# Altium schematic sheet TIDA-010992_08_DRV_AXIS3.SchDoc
size 431 x 279 mm; Date: Not shown in title block; ApprovedBy: Not shown in title block; CheckedBy: Not shown in title block; Author: Not shown in title block; CompanyName: Not shown in title block; Engineer: Not shown in title block; Organization: Not shown in title block; Address1: Not shown in title block; Address2: Not shown in title block; Address3: Not shown in title block; Address4: Not shown in title block; DocumentNumber: 8; Revision: Use project parameter SCH_Rev; SheetNumber: 8; SheetTotal: 13; PageSetup: Record=PageOptions¦CenterHorizontal=True¦CenterVertical=True¦PrintScale=1.00¦XCorrection=1.00¦YCorrection=1.00¦PrintKind=0¦BorderSize=5000000¦LeftOffset=0¦BottomOffset=0¦Orientation=2¦PaperLength=1000¦PaperWidth=1000¦Scale=100¦PaperSource=15¦PrintQuality=600¦MediaType=1¦DitherType=10¦PaperKind=Letter¦PrintScaleMode=1
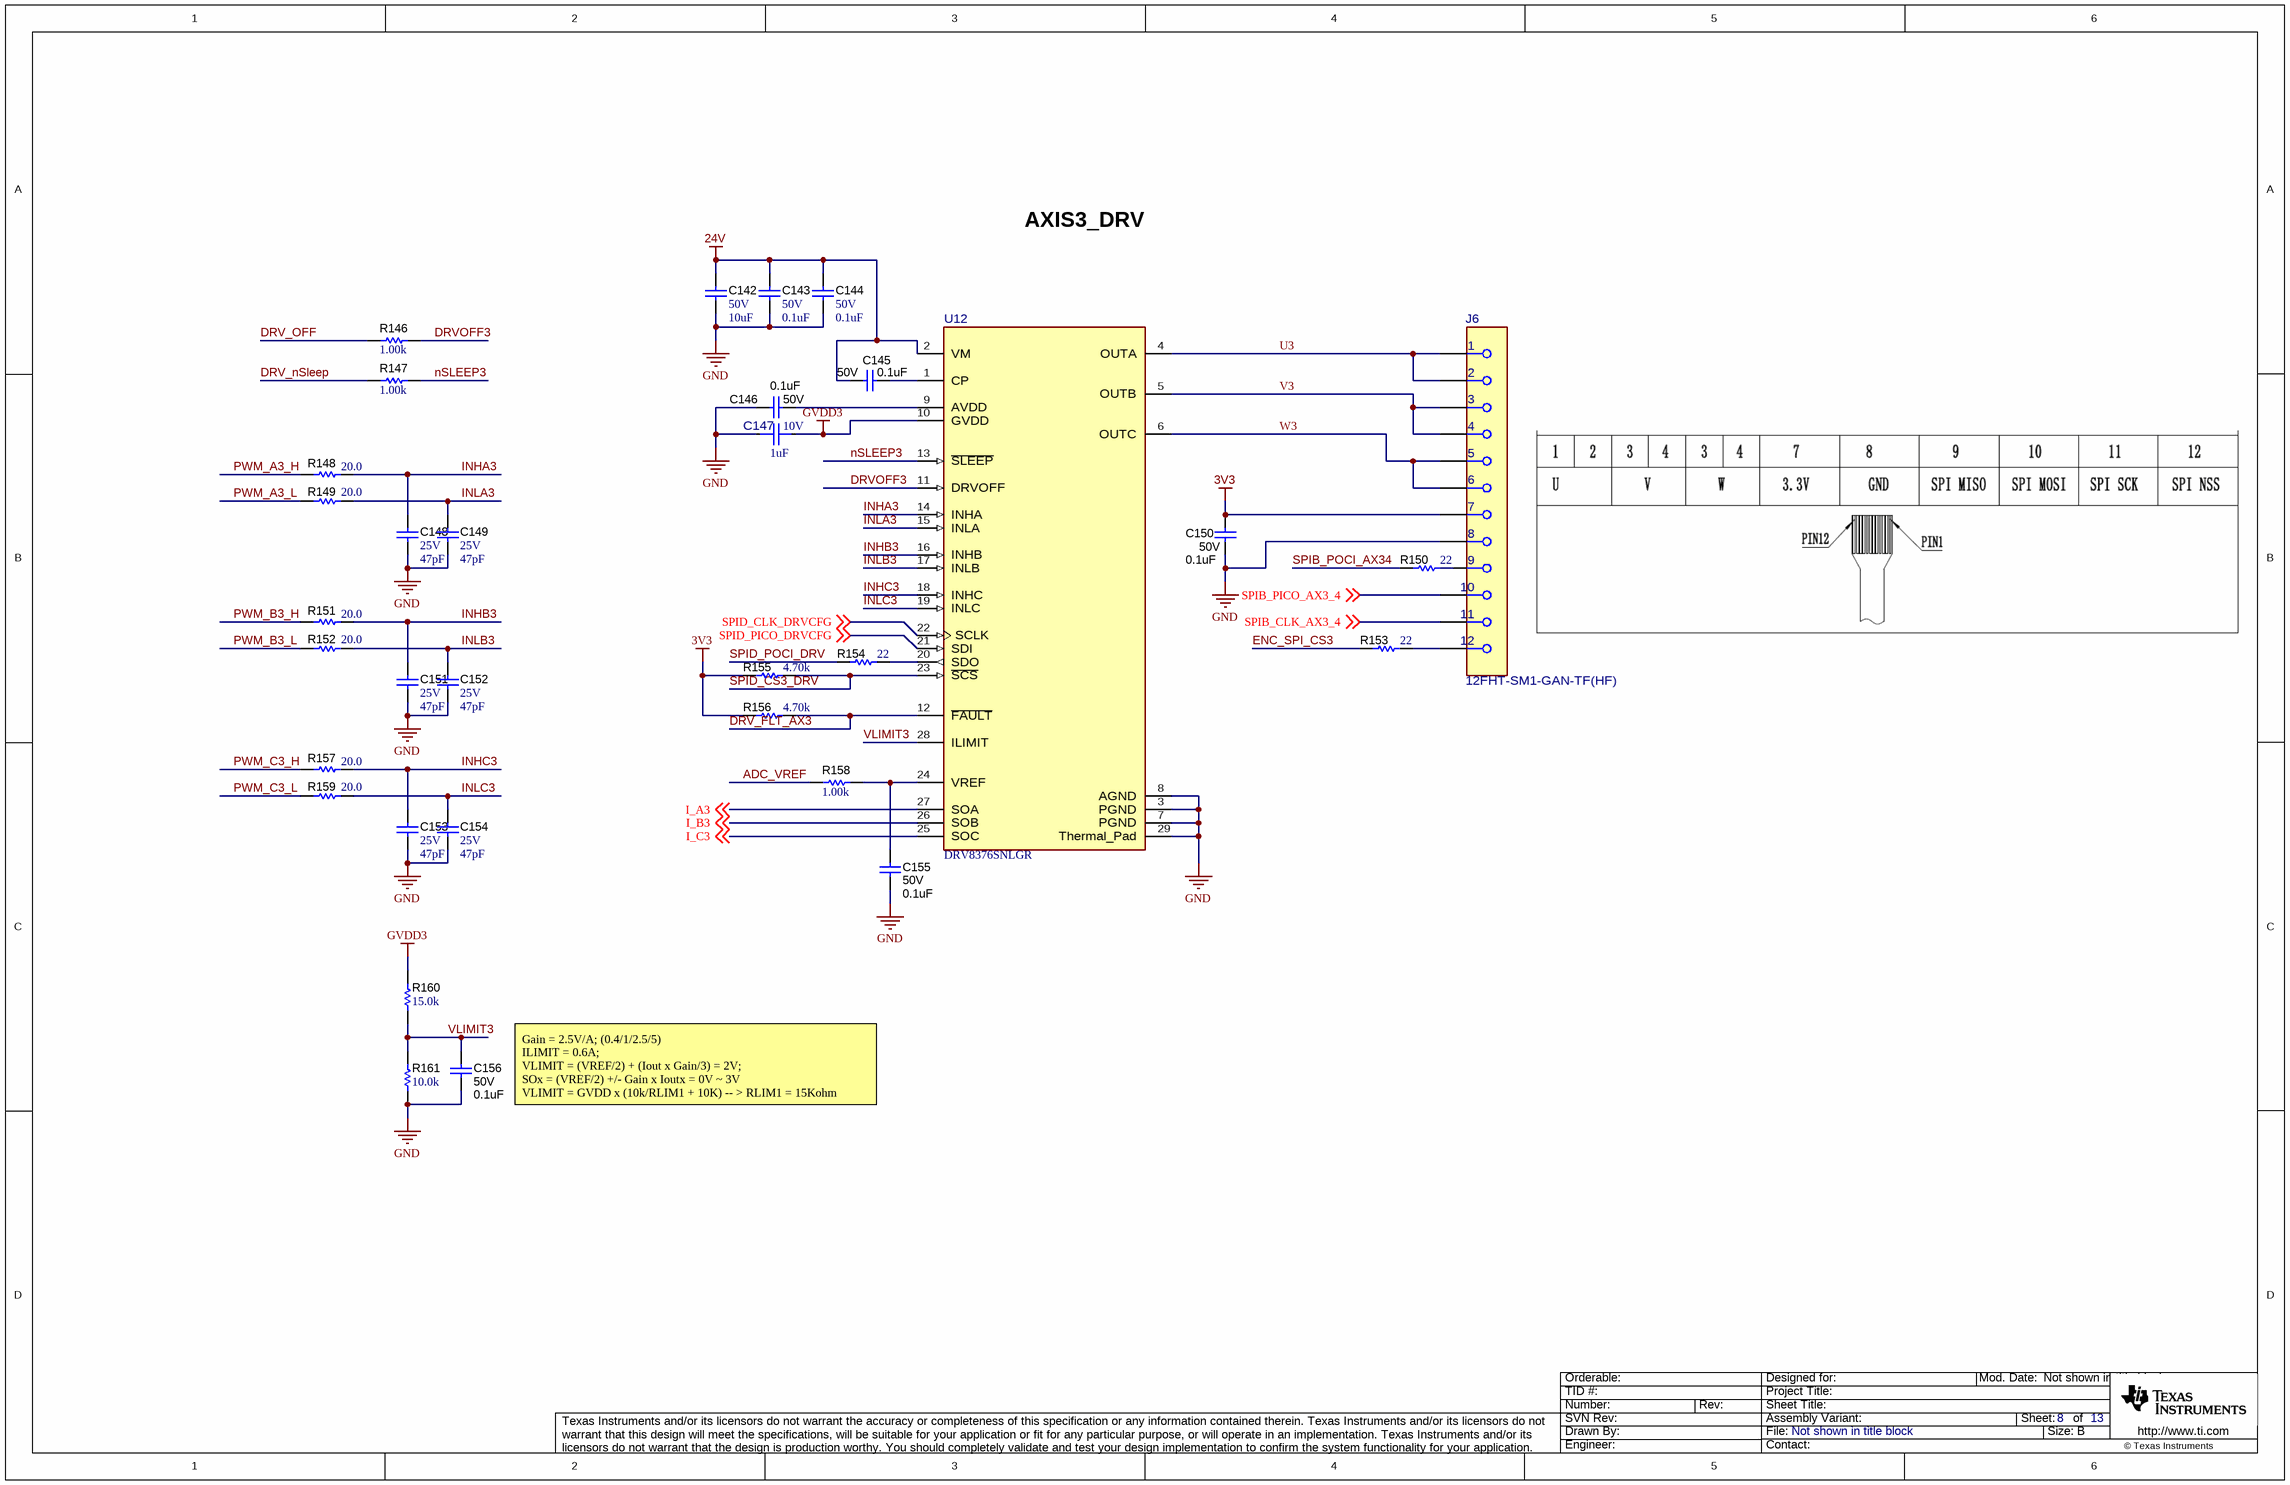
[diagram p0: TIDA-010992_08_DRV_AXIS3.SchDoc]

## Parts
C142  VDC_V: 50V  ValueDisplayed: 10uF  [1206_180]  (hidden comment: CL31B106KBHNNNE)
C143  VDC_V: 50V  ValueDisplayed: 0.1uF  [0402]  (hidden comment: C1005X7R1H104K050BE)
C144  VDC_V: 50V  ValueDisplayed: 0.1uF  [0402]  (hidden comment: C1005X7R1H104K050BE)
C145  VDC_V: 50V  ValueDisplayed: 0.1uF  [0402]  (hidden comment: CGA2B3X7R1H104M050BB)
C146  VDC_V: 50V  ValueDisplayed: 0.1uF  [0402]  (hidden comment: CGA2B3X7R1H104M050BB)
C147  VDC_V: 10V  ValueDisplayed: 1uF  [FP-GMC04X7R105K10NT_0402-MFG]  (hidden comment: GMC04X7R105K10NT)
C148  VDC_V: 25V  ValueDisplayed: 47pF  [0201_033]  (hidden comment: GRM0335C1E470JA01D)
C149  VDC_V: 25V  ValueDisplayed: 47pF  [0201_033]  (hidden comment: GRM0335C1E470JA01D)
C150  VDC_V: 50V  ValueDisplayed: 0.1uF  [0402]  (hidden comment: CGA2B3X7R1H104M050BB)
C151  VDC_V: 25V  ValueDisplayed: 47pF  [0201_033]  (hidden comment: GRM0335C1E470JA01D)
C152  VDC_V: 25V  ValueDisplayed: 47pF  [0201_033]  (hidden comment: GRM0335C1E470JA01D)
C153  VDC_V: 25V  ValueDisplayed: 47pF  [0201_033]  (hidden comment: GRM0335C1E470JA01D)
C154  VDC_V: 25V  ValueDisplayed: 47pF  [0201_033]  (hidden comment: GRM0335C1E470JA01D)
C155  VDC_V: 50V  ValueDisplayed: 0.1uF  [0402]  (hidden comment: CGA2B3X7R1H104M050BB)
C156  VDC_V: 50V  ValueDisplayed: 0.1uF  [0402]  (hidden comment: CGA2B3X7R1H104M050BB)
J6  12FHT-SM1-GAN-TF(HF)  [FP-12FHT-SM1-GAN-TF(HF)_CONN_FPC_12-MFG]
R146  ValueDisplayed: 1.00k  [0402]  (hidden comment: CRCW04021K00FKED)
R147  ValueDisplayed: 1.00k  [0402]  (hidden comment: CRCW04021K00FKED)
R148  ValueDisplayed: 20.0  [0201_033]  (hidden comment: CRCW020120R0FNED)
R149  ValueDisplayed: 20.0  [0201_033]  (hidden comment: CRCW020120R0FNED)
R150  ValueDisplayed: 22  [0201]  (hidden comment: ERJ-1GNJ220C)
R151  ValueDisplayed: 20.0  [0201_033]  (hidden comment: CRCW020120R0FNED)
R152  ValueDisplayed: 20.0  [0201_033]  (hidden comment: CRCW020120R0FNED)
R153  ValueDisplayed: 22  [0201]  (hidden comment: ERJ-1GNJ220C)
R154  ValueDisplayed: 22  [0201]  (hidden comment: ERJ-1GNJ220C)
R155  ValueDisplayed: 4.70k  [0201]  (hidden comment: RC0201FR-7D4K7L)
R156  ValueDisplayed: 4.70k  [0201]  (hidden comment: RC0201FR-7D4K7L)
R157  ValueDisplayed: 20.0  [0201_033]  (hidden comment: CRCW020120R0FNED)
R158  ValueDisplayed: 1.00k  [0402]  (hidden comment: CRCW04021K00FKED)
R159  ValueDisplayed: 20.0  [0201_033]  (hidden comment: CRCW020120R0FNED)
R160  ValueDisplayed: 15.0k  [0402]  (hidden comment: RC0402FR-0715KL)
R161  ValueDisplayed: 10.0k  [0402L]  (hidden comment: CRCW040210K0FKED)
U12  DRV8376SNLGR  [NLG0028A-MFG]

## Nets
3V3: C150.2 J6.7 R155.2 R156.2
24V: C142.1 C143.1 C144.1 C145.1 U12.2(VM)
GND: C142.2 C143.2 C144.2 C146.1 C147.1 C148.2 C149.2 C150.1 C151.2 C152.2 C153.2 C154.2 C155.1 C156.1 J6.8 R161.1 U12.3(PGND) U12.7(PGND) U12.8(AGND) U12.29(Thermal_Pad)
GVDD3: C147.2 R160.2 U12.10(GVDD)
ADC_VREF: R158.1
DRV_FLT_AX3: R156.1 U12.12(~{FAULT})
DRV_nSleep: R147.1
DRV_OFF: R146.1
DRVOFF3: R146.2 U12.11(DRVOFF)
ENC_SPI_CS3: R153.1
I_A3: U12.27(SOA) ; off-sheet I_A3
I_B3: U12.26(SOB) ; off-sheet I_B3
I_C3: U12.25(SOC) ; off-sheet I_C3
INHA3: C148.1 R148.2 U12.14(INHA)
INHB3: C151.1 R151.2 U12.16(INHB)
INHC3: C153.1 R157.2 U12.18(INHC)
INLA3: C149.1 R149.2 U12.15(INLA)
INLB3: C152.1 R152.2 U12.17(INLB)
INLC3: C154.1 R159.2 U12.19(INLC)
nSLEEP3: R147.2 U12.13(~{SLEEP})
PWM_A3_H: R148.1
PWM_A3_L: R149.1
PWM_B3_H: R151.1
PWM_B3_L: R152.1
PWM_C3_H: R157.1
PWM_C3_L: R159.1
SPIB_CLK_AX3_4: J6.11 ; off-sheet SPIB_CLK_AX3_4
SPIB_PICO_AX3_4: J6.10 ; off-sheet SPIB_PICO_AX3_4
SPIB_POCI_AX34: R150.1
SPID_CLK_DRVCFG: U12.22(SCLK) ; off-sheet SPID_CLK_DRVCFG
SPID_CS3_DRV: R155.1 U12.23(~{SCS})
SPID_PICO_DRVCFG: U12.21(SDI) ; off-sheet SPID_PICO_DRVCFG
SPID_POCI_DRV: R154.1
U3: J6.1 J6.2 U12.4(OUTA)
V3: J6.3 J6.4 U12.5(OUTB)
VLIMIT3: C156.2 R160.1 R161.2 U12.28(ILIMIT)
W3: J6.5 J6.6 U12.6(OUTC)
NetC145_2: C145.2 U12.1(CP)
NetC146_2: C146.2 U12.9(AVDD)
NetC155_2: C155.2 R158.2 U12.24(VREF)
NetJ6_9: J6.9 R150.2
NetJ6_12: J6.12 R153.2
NetR154_2: R154.2 U12.20(SDO)

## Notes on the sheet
- AXIS3_DRV
- Gain = 2.5V/A; (0.4/1/2.5/5)
  ILIMIT = 0.6A;
  VLIMIT = (VREF/2) + (Iout x Gain/3) = 2V;
  SOx = (VREF/2) +/- Gain x Ioutx = 0V ~ 3V
  VLIMIT = GVDD x (10k/RLIM1 + 10K) -- > RLIM1 = 15Kohm

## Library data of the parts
C142 = CMP-0008802-2: CAP, CERM, 10 uF, 50 V, +/- 10%, X7R, 1206; Manufacturer: Samsung; TaMin_C: -55°C; Polarized: N; SizeAreaWB_mm2: 10.92; Value1: Unknown; U/M: EA; Value: 10uF; TaMax_C: 125°C; SizeZ_mm: 1.8; SizeX_mm: 3.2; SizeY_mm: 1.6; Cap_Case: 1206; SizeArea_mm2: 5.12; Cap_F: 10µF; AEC Category: Q200
C143 C144 = CMP-0064946-2: CAP, CERM, 0.1 uF, 50 V,+/- 10%, X7R, 0402; Manufacturer: TDK; TaMin_C: -55°C; Polarized: N; SizeAreaWB_mm2: 3; Value1: Unknown; U/M: EA; Value: 0.1uF; TaMax_C: 125°C; SizeZ_mm: 0.6; SizeX_mm: 1; SizeY_mm: 0.5; Cap_F: 100nF; AEC Category: Q200
C145 C146 C150 C155 C156 = CMP-0006326-2: CAP, CERM, 0.1 uF, 50 V, +/- 20%, X7R, AEC-Q200 Grade 1, 0402; Manufacturer: TDK; TaMin_C: -55°C; Polarized: N; SizeAreaWB_mm2: 3; Value1: Unknown; U/M: EA; Value: 0.1uF; TaMax_C: 125°C; SizeZ_mm: 0.6; SizeX_mm: 1; SizeY_mm: 0.5; AEC Qualified: Y; Cap_F: 100nF; AEC Category: Q200
C147 = CMP-0093200-1: 1µF ±10% 10V Ceramic Capacitor X7R 0402 (1005 Metric); Manufacturer: Cal-Chip Electronics; TempCo: 15%; SizeZ_mm: 0.6mm; AEC Qualified: No
C148 C149 C151-C154 = CMP-0009662-3: CAP, CERM, 47 pF, 25 V, +/- 5%, C0G/NP0, 0201; Manufacturer: MuRata; TaMin_C: -55°C; Polarized: N; SizeAreaWB_mm2: 2.08; Value1: Unknown; U/M: EA; Value: 47pF; TaMax_C: 125°C; SizeZ_mm: 0.33; SizeX_mm: 0.6; SizeY_mm: 0.3; Cap_Case: 0201; SizeArea_mm2: 0.18; AEC Category: Q200
J6 = CMP-0126588-1: Conn FPC Connector F 12 POS 0.5mm Solder Ver SMD T/R; Manufacturer: JST; ContactFinish: Gold,Nickel; Current_A: 500mA; Voltage_V: 50V; AEC Qualified: No; Conn Gender: Female; Conn Orientation: Vertical; Is Female: yes; SizeZ_mm: 3.3mm; Standoff Height: 0.13mm
R146 R147 R158 = CMP-0026071-3: RES, 1.00 k, 1%, 0.063 W, AEC-Q200 Grade 0, 0402; Manufacturer: Vishay-Dale; Power_W: 63mW; TempCo: 100 ppm/C; Value_Code: 1k00; Value: 1.00k; EIA_Code: E96; Res_ohm: 1k; SizeX_mm: 1; SizeY_mm: 0.5; SizeZ_mm: 0.6; Value2: 0.063W; AEC Qualified: Y; VDC_V: 50V; AEC Category: Q200; AEC Grade: 0
R148 R149 R151 R152 R157 R159 = CMP-0078192-1: RES, 20.0, 1%, 0.05 W, 0201; Manufacturer: Vishay-Dale; Value_Code: 20R0; SizeArea_mm2: 0.18; AEC Qualified: N; AEC Category: Q200; Res_ohm: 20; Value: 20.0; SizeZ_mm: 0.33; EIA_Code: E96; TempCo: 200 ppm/C; Power_W: 50mW; VDC_V: 30V; SizeY_mm: 0.3; Value2: 0.05W; U/M: EA; SizeX_mm: 0.6
R150 R153 R154 = CMP-0027015-3: RES, 22, 5%, 0.05 W, AEC-Q200 Grade 1, 0201; Manufacturer: Panasonic; Power_W: 50mW; TempCo: 200 ppm/C; Value_Code: 22R0; U/M: EA; Value: 22; EIA_Code: E24; SizeX_mm: 0.6; SizeY_mm: 0.3; SizeZ_mm: 0.26; Value2: 0.05W; SizeArea_mm2: 0.18; AEC Qualified: Y; AEC Grade: 1; AEC Category: Q200
R155 R156 = CMP-0028031-1: RES, 4.70 k, 1%, 0.05 W, 0201; Manufacturer: Yageo America; Power_W: 50mW; TempCo: 200 ppm/C; Value_Code: 4k70; U/M: EA; Value: 4.70k; Res_ohm: 4.7k; SizeX_mm: 0.6; SizeY_mm: 0.3; SizeZ_mm: 0.26; Value2: 0.05W; SizeArea_mm2: 0.18; AEC Qualified: N; VDC_V: 25V; AEC Category: Q200
R160 = CMP-0078583-1: RES, 15.0 k, 1%, 0.063 W, 0402; Manufacturer: Yageo America; Power_W: 63mW; Green_Lifecycle: Active; TempCo: 100 ppm/C; Value_Code: 15k0; Green_REACh: Passed; Value: 15.0k; EIA_Code: E96; Res_ohm: 15k; SizeX_mm: 1; SizeY_mm: 0.5; SizeZ_mm: 0.6; Value2: 0.063W; AEC Qualified: N; AEC Category: Q200
R161 = CMP-0025958-3: RES, 10.0 k, 1%, 0.063 W, AEC-Q200 Grade 0, 0402; Manufacturer: Vishay-Dale; Power_W: 63mW; TempCo: 100 ppm/C; Value_Code: 10k0; Value: 10.0k; EIA_Code: E96; Res_ohm: 10k; SizeX_mm: 1; SizeY_mm: 0.5; SizeZ_mm: 0.6; Value2: 0.063W; AEC Qualified: Y; VDC_V: 50V; AEC Category: Q200; AEC Grade: 0
U12 = CMP-0122073-1: Three-Phase Integrated FET Motor Driver; Manufacturer: Texas Instruments; SizeZ_mm: 1mm; AEC Qualified: No; Max Supply Voltage: 65V; Min Supply Voltage: 4.5V; Motor Type: Brushless DC; Nominal Supply Current: 6.6-8.2mA; Number Of Outputs: 3; Standoff Height: 0mm; Switching Frequency: 100kHz; TaMax_C: +125°C; TaMin_C: -40°C; TJmax_C: +150°C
